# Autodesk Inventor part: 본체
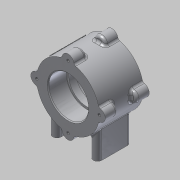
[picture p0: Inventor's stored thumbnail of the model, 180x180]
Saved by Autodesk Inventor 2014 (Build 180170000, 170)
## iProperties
Created: 2015-03
Part Number: 본체
Material: 알루미늄 6061
Document SubType Name: Modeling
Designer: MYHOME
Mass: 450.776 g
Surface Area: 332.745 cm^2
Volume: 166.338 cm^3
Density: 2.71 g/cm^3
Appearance: 알루미늄 - 평지
Author: MYHOME
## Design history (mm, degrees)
sketch "스케치2"
  geometry: C1 r 37 at (0, 0); 1 further point
  constraints: 1 centre point, 1 coincident
  dimensions: "d0" = 74 diameter of C1
extrude "돌출1" new body sketch "스케치2" stored distance "d1" = 52; taper "d2" = 0 deg
sketch "스케치3"
  geometry: C1 r 7 at (-37, 0); C2 r 7 at (0, 37); C3 r 7 at (37, 0); C4 r 7 at (0, -37); A1 r 37 centre (0, 0) between (-37, 0) and (0, 37) reference
  constraints: 4 centre point, 4 point on circle, 3 equal radius, 2 horizontal alignment, 2 vertical alignment
  dimensions: "d4" = 7 radius of C1
extrude "돌출2" join sketch "스케치3" distance "d5" = 15; taper "d6" = 0 deg
sketch "스케치4"
  geometry: A1 r 7 centre (37, 0) between (36.338, -6.969) and (36.338, 6.969) reference; A2 r 7 centre (0, 37) between (6.969, 36.338) and (-6.969, 36.338) reference; A3 r 7 centre (-37, 0) between (-36.338, 6.969) and (-36.338, -6.969) reference; A4 r 7 centre (0, -37) between (-6.969, -36.338) and (6.969, -36.338) reference
hole "구멍1" sketch "스케치4" at (0, 37), (37, 0), (0, -37), (-37, 0) diameter "d7" = 3.242; stored, may be unused: countersink angle "d11" = 90 deg, drill point angle "d13" = 118 deg; dims "d8" = 8, "d9" = 4, "d10" = 2, "d12" = 11
fillet "모깎기1" dims "d14" = 3
sketch "스케치6"
  geometry: C1 r 23.5 at (0, 0); A1 r 37 centre (0, 0) between (-35.863, -9.104) and (-9.104, -35.863) reference
  constraints: 1 centre point, 1 coincident
  dimensions: "d21" = 47 diameter of C1
extrude "돌출4" cut sketch "스케치6" distance "d22" = 22; taper "d23" = 0 deg
chamfer "모따기2" distance "d24" = 1; stored, may be unused: second distance "d25" = 2, angle "d26" = 45 deg
sketch "스케치7"
  geometry: C1 r 23.5 at (0, 0); A1 r 37 centre (0, 0) between (35.863, 9.104) and (9.104, 35.863) reference
  constraints: 1 centre point, 1 coincident
  dimensions: "d27" = 47 diameter of C1
extrude "돌출5" cut sketch "스케치7" distance "d28" = 22; taper "d29" = 0 deg
chamfer "모따기3" distance "d30" = 1; stored, may be unused: second distance "d31" = 2, angle "d32" = 45 deg
sketch "스케치8"
  geometry: C1 r 23.5 at (0, 0) reference; C2 r 21 at (0, 0)
  constraints: 1 centre point, 1 coincident
  dimensions: "d33" = 42 diameter of C2
extrude "돌출6" cut sketch "스케치8" stored distance "d34" = 22; taper "d35" = 0 deg
fillet "모깎기2" dims "d36" = 0.3
node "작업 평면1"
sketch "스케치10"
  geometry: L1 (24, -15)-(24, 15); L2 (29, -15)-(29, 15); L3 (19, 15)-(19, -15); L4 (-24, -15)-(-24, 15); L5 (-19, -15)-(-19, 15); L6 (-29, 15)-(-29, -15); A1 r 5 centre (24, -15) between (19, -15) and (29, -15); A2 r 5 centre (24, 15) between (29, 15) and (19, 15); A3 r 5 centre (-24, -15) between (-29, -15) and (-19, -15); A4 r 5 centre (-24, 15) between (-19, 15) and (-29, 15); 3 further points
  constraints: 16 end point, 8 point on circle, 8 tangent, 4 centre point, 3 parallel, 2 horizontal alignment, 2 midpoint, 1 vertical
  dimensions: "d38" = 48 distance of L1.start L4.start; "d39" = 40 dimension on A2 A1; "d40" = 40 dimension on A4 A3; "d41" = 24 distance of point (-24, 0) point (0, 0); "d42" = 5 radius of A4; "d43" = 5 radius of A2
extrude "돌출7" join sketch "스케치10" stored distance "d44" = 22; taper "d45" = 0 deg
sketch "스케치11"
  geometry: L1 (29, -15)-(29, 15) reference; L2 (19, 15)-(19, -15) reference; A1 r 5 centre (-24, 15) between (-19, 15) and (-29, 15) reference; A2 r 5 centre (-24, -15) between (-29, -15) and (-19, -15) reference; A3 r 5 centre (24, 15) between (29, 15) and (19, 15) reference; A4 r 5 centre (24, -15) between (19, -15) and (29, -15) reference; 1 further point
hole "구멍2" sketch "스케치11" at (-24, -15), (-24, 15), (24, -15), (24, 15) diameter "d46" = 4.134; stored, may be unused: countersink angle "d50" = 90 deg, drill point angle "d52" = 118 deg; dims "d47" = 6, "d48" = 4, "d49" = 2, "d51" = 8
fillet "모깎기3" dims "d53" = 3
sketch "스케치12"
  geometry: L1 (0, 0)-(37, 0); L2 (0, 0)-(26.163, 26.163); A1 r 37 centre (0, 0) between (35.863, 9.104) and (9.104, 35.863) reference; A2 r 37 centre (0, 0) between (36.913, -2.543) and (36.913, 2.543) reference; 2 further points
  constraints: 4 end point, 2 point on circle, 1 coincident, 1 horizontal
  dimensions: "d54" = 45 deg angle of L1 L2
node "작업 평면2"
sketch "스케치13"
  geometry: L1 (-26, 18.921)-(-26, -18.921) reference; 2 further points
  constraints: 1 coincident, 1 other
  dimensions: "d55" = 26 distance from line of point (0, 0) L1
feature "엠보싱1" sketch "스케치13" dims "d56" = 0.5, "d57" = 0
node "솔리드1"
mirror "대칭1"
node "투영된 루프1"
other parameters: "d37" = -56
